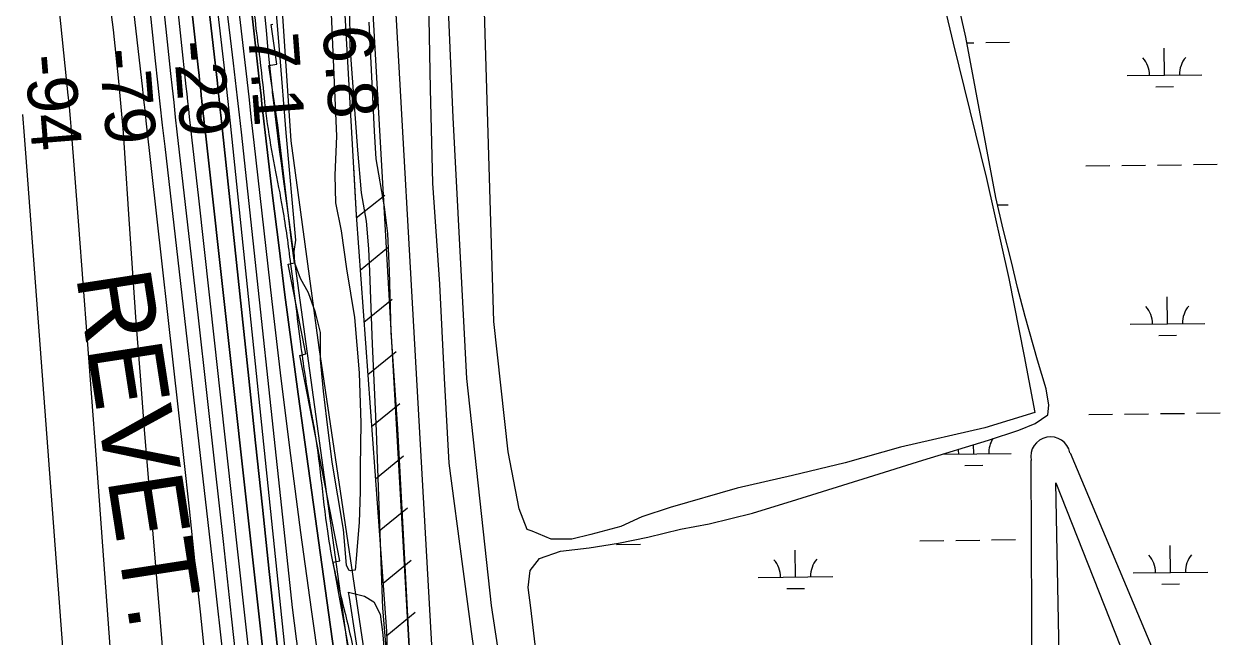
# Model space of a CAD drawing. Extents: x 3694830 to 3732949, y 415201 to 440970.
# Drawn here: x 3718390 to 3720008, y 423717 to 424536 of the extents above; entities that cross this region are included whole.
import ezdxf

# ---------------------------------------------------------------- set-up
doc = ezdxf.new("R2010")
doc.units = 0
for name, color, linetype in [('V-FLOD-BASE', 7, 'Continuous'), ('V-LEVE-TOET', 7, 'Continuous'), ('V-RIVR-EDGE', 7, 'Continuous'), ('V-RIVR-RANG', 7, 'Continuous'), ('V-ROAD-CNTR', 7, 'Continuous'), ('V-RRAP-FSHR', 7, 'Continuous'), ('V-RRAP-RVMT', 7, 'Continuous'), ('V-RRAP-RVMT-IDEN', 7, 'Continuous'), ('V-SITE-VEGE', 7, 'Continuous'), ('V-SURV-LINE', 7, 'Continuous'), ('V-TOPO-DPTH', 7, 'Continuous'), ('V-TOPO-MAJR', 7, 'Continuous'), ('V-TOPO-MINR', 7, 'Continuous'), ('V-TOPO-WATR', 7, 'Continuous'), ('V-TOPO-WATR-IDEN', 7, 'Continuous'), ('V-WETL-SWMP', 7, 'Continuous')]:
    doc.layers.add(name, color=color, linetype=linetype)

msp = doc.modelspace()

# ---------------------------------------------------------------- linework, layer by layer
at = {"layer": 'V-FLOD-BASE'}
msp.add_lwpolyline([(3719080, 422624.3), (3719063, 422730.6), (3719042.5, 422855.9), (3719023.9, 422955), (3718998.7, 423105.1), (3718976, 423242.3), (3718950.3, 423388.8), (3718931.8, 423489.9), (3718918.9, 423582.8), (3718912.7, 423621.4), (3718909.6, 423642.6), (3718908.1, 423662.7), (3718904.5, 423727.2), (3718897.9, 423854.1), (3718890.2, 423994.9), (3718881.4, 424124.4), (3718878.9, 424206.4), (3718876.9, 424256.4), (3718872.2, 424292), (3718861.4, 424356), (3718858.8, 424393.1), (3718851.7, 424539.1)], dxfattribs=at)
at = {"layer": 'V-LEVE-TOET'}
for points in [[(3719118.2, 422780.4), (3719107.6, 422885.7), (3719094.9, 423003.7), (3719080, 423116.4), (3719049.3, 423317.4), (3719031.2, 423440.8), (3719014.3, 423552.4), (3718999.4, 423646), (3718988.8, 423723.6), (3718977.1, 423810.8), (3718959.1, 423949.1), (3718952.8, 424062.8), (3718946.4, 424188.3), (3718936.9, 424323.4), (3718933.8, 424449.9), (3718931.7, 424566.9), (3718926.4, 424699.8), (3718917.9, 424783.8), (3718910.5, 424881.6), (3718901, 424966.7), (3718901, 425006.1), (3718898.9, 425044.3), (3718900, 425078.4)], [(3718995.1, 422968.1), (3718965.4, 423137.2), (3718928.2, 423349.9), (3718893.2, 423534.9), (3718884.7, 423580.7), (3718880.5, 423621.1), (3718877.3, 423670), (3718869.9, 423755.1), (3718865.7, 423879.5), (3718861.5, 423992.2), (3718856.2, 424108.1), (3718852.5, 424205.4), (3718851.4, 424235.7), (3718848.3, 424272.9), (3718841.4, 424310.7), (3718836.6, 424367.6), (3718826.6, 424506.9), (3718825.5, 424612.7)]]:
    msp.add_lwpolyline(points, dxfattribs=at)
at = {"layer": 'V-RIVR-EDGE'}
msp.add_spline([(3716285.2, 433216.7), (3716310.4, 433178.2), (3716330.2, 433149.7), (3716351.4, 433122.5), (3716380.7, 433076.8), (3716399.1, 433050.5), (3716447.8, 432976.2), (3716475.3, 432930.5), (3716501.8, 432891.1), (3716527.5, 432851.2), (3716586, 432749.3), (3716608.1, 432711.8), (3716608.1, 432707.7), (3716608.1, 432700.4), (3716613, 432690.9), (3716627.4, 432664.2), (3716633.3, 432651.6), (3716643.2, 432639.3), (3716675.2, 432589.5), (3716706.2, 432538.3), (3716726.9, 432498), (3716741.3, 432463.6), (3716748.5, 432442.8), (3716788.6, 432378.5), (3716817.4, 432339.6), (3716842.2, 432297.4), (3716889.5, 432209.6), (3716920.5, 432144.4), (3716938, 432109.6), (3716956.5, 432075.2), (3716988.9, 432022.6), (3717009.2, 431986.9), (3717026.3, 431960.1), (3717062.3, 431897.6), (3717093.4, 431840.1), (3717112.3, 431799.9), (3717149.1, 431711.1), (3717176.5, 431644.6), (3717201.2, 431580.8), (3717210.7, 431556.4), (3717248.5, 431478.9), (3717267.8, 431435.5), (3717289.4, 431392.9), (3717306.5, 431346.8), (3717328.1, 431301), (3717339.3, 431276.6), (3717352.3, 431244), (3717362.7, 431226.4), (3717376.2, 431205.5), (3717389.3, 431178.4), (3717401.4, 431141.7), (3717407.2, 431113.2), (3717409.9, 431101.9), (3717419.7, 431075.6), (3717452.5, 430968.9), (3717469.1, 430916.8), (3717483.4, 430865.2), (3717505.5, 430810), (3717526.6, 430753.4), (3717540.5, 430715.4), (3717579.1, 430593.2), (3717599.3, 430526.3), (3717616.3, 430474.7), (3717628.9, 430437.1), (3717638.7, 430405), (3717647.7, 430364.3), (3717653.5, 430331.7), (3717658.4, 430314.5), (3717667.9, 430290.1), (3717679.5, 430260.7), (3717690.3, 430242.1), (3717695.7, 430221.3), (3717698.4, 430200), (3717697.9, 430172), (3717701.4, 430153), (3717705.9, 430140.8), (3717716.3, 430119.9), (3717728, 430100.5), (3717735.6, 430076.5), (3717737.8, 430059.3), (3717749, 430029.9), (3717760.8, 430011.8), (3717771.6, 429990), (3717776.5, 429968.3), (3717783.2, 429941.6), (3717791.7, 429917.6), (3717803.4, 429898.6), (3717812.4, 429876.5), (3717819.2, 429857.4), (3717834.9, 429816.7), (3717846.5, 429770.1), (3717854.1, 429734.8), (3717863.5, 429706.3), (3717878.8, 429667.4), (3717891.4, 429622.6), (3717903.5, 429586.4), (3717917.8, 429530.3), (3717931.7, 429476.4), (3717959.5, 429363.8), (3717976.5, 429307.2), (3717987.2, 429262.4), (3718014.1, 429153.9), (3718027.5, 429090.1), (3718040.5, 429028.1), (3718052.5, 428962.5), (3718057.8, 428920), (3718056.9, 428903.3), (3718056.9, 428887.9), (3718057.7, 428868.4), (3718061.3, 428850.8), (3718065.8, 428833.6), (3718082.4, 428779.3), (3718091.3, 428748.1), (3718100.3, 428711), (3718111.4, 428657.1), (3718116.4, 428631.8), (3718128.3, 428526), (3718136.8, 428473.1), (3718141.7, 428440), (3718152.3, 428360.9), (3718163.9, 428291.2), (3718171, 428256.4), (3718178.2, 428236.5), (3718193.9, 428178.6), (3718199.7, 428157.3), (3718197.9, 428150.1), (3718196.5, 428133.3), (3718197.4, 428121.1), (3718204.1, 428098), (3718215.4, 428075.4), (3718228, 428049.6), (3718240.1, 428011.6), (3718242.7, 427978.6), (3718251.1, 427901.2), (3718254.2, 427852.9), (3718257.7, 427822.1), (3718271.5, 427736.2), (3718281.7, 427671.9), (3718287.9, 427606.3), (3718295.9, 427551.6), (3718303.9, 427477.4), (3718310.1, 427447.1), (3718323.1, 427407.8), (3718345.1, 427350.3), (3718351.4, 427321.8), (3718363.5, 427267.5), (3718378.3, 427217.3), (3718398, 427141.2), (3718402.9, 427105.5), (3718405.9, 427056.7), (3718404.9, 426993.4), (3718419.6, 426915.1), (3718427.1, 426857.7), (3718428.8, 426789.8), (3718439.5, 426753.2), (3718453.9, 426709.8), (3718458.3, 426677.2), (3718461.8, 426625.2), (3718465.3, 426583.6), (3718482.7, 426479.5), (3718492.5, 426423.9), (3718501, 426378.2), (3718502.7, 426350.2), (3718512.9, 426256.1), (3718518.2, 426213.1), (3718524, 426182.8), (3718533.4, 426148.9), (3718540.9, 426069.3), (3718548.9, 426010.9), (3718557.8, 425944.4), (3718573.4, 425858.9), (3718584.5, 425787.5), (3718587.6, 425745.4), (3718587.6, 425726), (3718607.5, 425567.2), (3718614.6, 425488.1), (3718638.2, 425368.6), (3718641.3, 425318.4), (3718641.1, 425249.7), (3718640.1, 425214), (3718649.8, 425130.8), (3718658.7, 425069.3), (3718661.8, 425037.2), (3718660.4, 425016.4), (3718675, 424864.4), (3718675.7, 424812.8), (3718692.6, 424694.8), (3718696.1, 424618.8), (3718696.4, 424575.9), (3718706.1, 424484.5), (3718711.9, 424431.6), (3718715.4, 424403.1), (3718735.9, 424289.1), (3718746.6, 424215.4), (3718759.9, 424108.6), (3718772.4, 424027.2), (3718777.7, 423998.3), (3718795.9, 423858), (3718805.7, 423804.2), (3718812.4, 423776.6), (3718829, 423707.4), (3718835.7, 423662.6), (3718835.1, 423612), (3718835, 423576.7), (3718839.3, 423505.3), (3718842.4, 423460), (3718850.4, 423412.5), (3718863.4, 423357.8), (3718870.6, 423326.6), (3718873.6, 423260.5), (3718878.9, 423209), (3718893.6, 423148.4), (3718899, 423126.2), (3718912.4, 423080), (3718927.2, 423022.6), (3718930.8, 422992.7), (3718937.4, 422950.2), (3718945.9, 422900.5), (3718952.6, 422870.6), (3718968.7, 422795.9), (3718969.6, 422769.7), (3718968.1, 422738.5), (3718972.1, 422707.8), (3718981, 422661.2), (3718990.8, 422602.8), (3719006.9, 422506.5), (3719010.8, 422446.3), (3719014.4, 422425.1), (3719022.4, 422393.4), (3719033.2, 422359), (3719050.3, 422307.9), (3719062.8, 422249.1), (3719077.1, 422190.2), (3719087.8, 422149.1)], degree=3, dxfattribs=at)
at = {"layer": 'V-ROAD-CNTR'}
msp.add_lwpolyline([(3718947.5, 424793.9), (3718964, 424411.4), (3718982.2, 424062.3), (3719015.2, 423758.3), (3719087.3, 423283.5), (3719154, 422831.8), (3719191.5, 422587.8), (3719255.9, 422328.3), (3719350.6, 422063.9), (3719444.2, 421874.4), (3719568.8, 421676.5), (3719728.1, 421465.7), (3719881.2, 421306.9), (3720024.6, 421178.6), (3720151.9, 421084.4), (3720292.9, 420993.4), (3720460.7, 420905.9), (3720538.9, 420876)], dxfattribs=at)
at = {"layer": 'V-RRAP-FSHR'}
for p, q in [((3718834.5, 424277.1), (3718872.9, 424307.3)), ((3718839.7, 424207.3), (3718877.6, 424238.2)), ((3718844.8, 424137.5), (3718882.7, 424168.3)), ((3718849.9, 424067.7), (3718887.8, 424098.5)), ((3718855, 423997.9), (3718892.9, 424028.7)), ((3718860.1, 423928.1), (3718898, 423958.9)), ((3718865.2, 423858.3), (3718903.1, 423889.1)), ((3718870.4, 423788.4), (3718908.2, 423819.3)), ((3718875.5, 423718.6), (3718913.3, 423749.5))]:
    msp.add_line(p, q, dxfattribs=at)
for points in [[(3718391.1, 427348.3), (3718475.5, 426733.1), (3718537.6, 426315.3), (3718574.7, 426010.6), (3718621.1, 425693.6), (3718655.8, 425402.4), (3718689.1, 424990.9), (3718733.5, 424580.7), (3718747, 424380.1), (3718784.4, 424103.6), (3718845.2, 423695.1), (3718886.1, 423421.6), (3718923.4, 423190.5), (3718957.4, 423026.2), (3718988.3, 422871.6), (3719013.6, 422718), (3719111.7, 422210.5), (3719157, 422005.7), (3719219.8, 421828), (3719374.7, 421477.8), (3719529.6, 421100.8)], [(3718800.8, 424873.2), (3718834.3, 424280.7), (3718875.1, 423724.2), (3718879.1, 423600.7), (3718900.6, 423436), (3718998.4, 422905.1), (3719048.2, 422575.2), (3719088.2, 422325.5), (3719124.8, 422190.6), (3719167, 422050.6), (3719263.7, 421833.4), (3719401.6, 421600.1), (3719571.7, 421363.5), (3719742.7, 421175.3), (3719823.1, 421106.3)], [(3718830.7, 424345.4), (3718834.3, 424280.7), (3718875.1, 423724.2), (3718878, 423633.2)]]:
    msp.add_lwpolyline(points, dxfattribs=at)
at = {"layer": 'V-RRAP-RVMT'}
for p, q in [((3718720.7, 424535.9), (3718722.9, 424536.3)), ((3718728.2, 424482.9), (3718720.7, 424535.9)), ((3718717.4, 424480.9), (3718728.2, 424482.9)), ((3718729.7, 424401.2), (3718717.4, 424480.9)), ((3718747.9, 424246.5), (3718729.7, 424401.2)), ((3718752, 424216.9), (3718747.9, 424246.5)), ((3718743.2, 424215), (3718752, 424216.9)), ((3718767.2, 424095.2), (3718743.2, 424215)), ((3718759, 424093), (3718767.2, 424095.2)), ((3718812.5, 423818.3), (3718759, 424093)), ((3718803.8, 423816.5), (3718812.5, 423818.3)), ((3718825.9, 423693.4), (3718803.8, 423816.5))]:
    msp.add_line(p, q, dxfattribs=at)
at = {"layer": 'V-SITE-VEGE'}
for points in [[(3719580.5, 424734), (3719633.6, 424510.7), (3719678.2, 424329.9), (3719707.9, 424195.9), (3719728.5, 424092.2), (3719742.6, 424016.8), (3719676, 423996), (3719563.2, 423970.5), (3719488.8, 423949.3), (3719418.6, 423932.3), (3719344.2, 423915.3), (3719254.8, 423889.8), (3719216.6, 423877), (3719188.9, 423864.3), (3719148.5, 423853.7), (3719123, 423847.3), (3719095.3, 423847.3), (3719069.8, 423858), (3719063.4, 423860.1), (3719052.8, 423887.7), (3719037.9, 423964.3), (3719018.9, 424138.7), (3719006.3, 424553.4)], [(3718798.4, 424611.9), (3718807.9, 424386.5), (3718805.7, 424334.4), (3718806.8, 424297.2), (3718814.2, 424259.9), (3718821.6, 424208.9), (3718832.3, 424144), (3718838.6, 424069.6), (3718840.7, 424002.6), (3718839.6, 423944.1), (3718839.6, 423911.1), (3718838.5, 423869.7), (3718836.4, 423843.1), (3718834.3, 423820.8), (3718833.2, 423805.9), (3718826.8, 423804.8), (3718824.7, 423805.9), (3718821.5, 423812.3), (3718817.3, 423860.1), (3718802.4, 423950.5), (3718795, 424007.9), (3718790.8, 424045.1), (3718786.5, 424087.7), (3718786.5, 424123.8), (3718780.2, 424150.4), (3718770.6, 424177), (3718760, 424196.2), (3718752.5, 424216.4), (3718751.5, 424232.3), (3718753.6, 424247.2), (3718740.9, 424390.8), (3718732.4, 424497.1), (3718714.4, 424710.8)]]:
    msp.add_lwpolyline(points, dxfattribs=at)
at = {"layer": 'V-SURV-LINE'}
for points in [[(3718860.6, 425023.9), (3718941.6, 423595.4)], [(3718911.6, 423593.7), (3718830.6, 425022.2)]]:
    msp.add_lwpolyline(points, dxfattribs=at)
at = {"layer": 'V-TOPO-DPTH'}
for points in [[(3718536.6, 425258.5), (3718623.3, 424474.8), (3718624.1, 424468.1), (3718624.8, 424461.3), (3718625.6, 424454.5), (3718626.3, 424447.7), (3718627.6, 424436), (3718627.7, 424435.1), (3718627.8, 424434.1), (3718627.9, 424433.2), (3718628, 424432.3), (3718629.1, 424422.2), (3718629.8, 424416.3), (3718630.4, 424410.3), (3718631.1, 424404.4), (3718631.7, 424398.4), (3718722.8, 423578.2)], [(3718536.6, 425258.5), (3718623.3, 424474.8), (3718624.1, 424468.1), (3718624.8, 424461.3), (3718625.6, 424454.5), (3718626.3, 424447.7), (3718627.6, 424436), (3718627.7, 424435.1), (3718627.8, 424434.1), (3718627.9, 424433.2), (3718628, 424432.3), (3718629.1, 424422.2), (3718629.8, 424416.3), (3718630.4, 424410.3), (3718631.1, 424404.4), (3718631.7, 424398.4), (3718722.8, 423578.2)], [(3719042.8, 422082), (3718907.4, 422824.3), (3718862.2, 423105.4), (3718849.9, 423179.3), (3718836.9, 423253.1), (3718823.1, 423326.7), (3718808.6, 423400.2), (3718794.8, 423468.2), (3718787.1, 423507.7), (3718779.8, 423547.2), (3718773.1, 423586.8), (3718766.8, 423626.5), (3718766.2, 423630.4), (3718760.2, 423672.1), (3718754.5, 423713.9), (3718749.4, 423755.7), (3718744.6, 423797.6), (3718680.8, 424391.8), (3718678.3, 424414.8), (3718675.7, 424437.8), (3718673, 424460.9), (3718670.3, 424483.9), (3718583, 425211.4)], [(3719042.8, 422082), (3718907.4, 422824.3), (3718862.2, 423105.4), (3718849.9, 423179.3), (3718836.9, 423253.1), (3718823.1, 423326.7), (3718808.6, 423400.2), (3718794.8, 423468.2), (3718787.1, 423507.7), (3718779.8, 423547.2), (3718773.1, 423586.8), (3718766.8, 423626.5), (3718766.2, 423630.4), (3718760.2, 423672.1), (3718754.5, 423713.9), (3718749.4, 423755.7), (3718744.6, 423797.6), (3718680.8, 424391.8), (3718678.3, 424414.8), (3718675.7, 424437.8), (3718673, 424460.9), (3718670.3, 424483.9), (3718583, 425211.4)], [(3718627, 424647.6), (3718648.6, 424457.2), (3718649.8, 424446.6), (3718651, 424435.9), (3718652.1, 424425.3), (3718653.3, 424414.6), (3718690.7, 424062.2), (3718699.9, 423976.2), (3718709.1, 423890.1), (3718718.2, 423804.1), (3718727.4, 423718.1), (3718744.3, 423559.5)], [(3718744.3, 423559.5), (3718727.4, 423718.1), (3718718.2, 423804.1), (3718709.1, 423890.1), (3718699.9, 423976.2), (3718690.7, 424062.2), (3718653.3, 424414.6), (3718652.1, 424425.3), (3718651, 424435.9), (3718649.8, 424446.6), (3718648.6, 424457.2), (3718627, 424647.6)], [(3718689.2, 424604.5), (3718704.6, 424462.5), (3718705.8, 424451.4), (3718707.1, 424440.3), (3718708.3, 424429.2), (3718709.6, 424418.1), (3718722.6, 424307.2), (3718730.7, 424240.7), (3718739, 424174.2), (3718747.7, 424107.8), (3718756.7, 424041.4), (3718820.4, 423582.2)], [(3718701.9, 423596.3), (3718652.5, 424044.6), (3718645.4, 424109.3), (3718638.2, 424174), (3718631, 424238.7), (3718623.7, 424303.4), (3718611.5, 424412.3), (3718610.3, 424422.5), (3718609.2, 424432.7), (3718608.1, 424442.9), (3718607, 424453.1), (3718593.5, 424579.9)], [(3718701.9, 423596.3), (3718652.5, 424044.6), (3718645.4, 424109.3), (3718638.2, 424174), (3718631, 424238.7), (3718623.7, 424303.4), (3718611.5, 424412.3), (3718610.3, 424422.5), (3718609.2, 424432.7), (3718608.1, 424442.9), (3718607, 424453.1), (3718593.5, 424579.9)]]:
    msp.add_lwpolyline(points, dxfattribs=at)
at = {"layer": 'V-TOPO-MAJR'}
for points in [[(3718681.9, 423613.8), (3718667.7, 423744.1), (3718656.7, 423844), (3718645.7, 423943.8), (3718634.5, 424043.6), (3718623.3, 424143.4), (3718595, 424392.3), (3718592.8, 424411.8), (3718590.7, 424431.3), (3718588.5, 424450.7), (3718586.5, 424470.2), (3718549.4, 424821.9)], [(3718445.6, 423649.3), (3718392.7, 424357.7), (3718390.4, 424386.7), (3718388.2, 424415.6)]]:
    msp.add_lwpolyline(points, dxfattribs=at)
at = {"layer": 'V-TOPO-MINR'}
for points in [[(3718722.8, 423578.2), (3718631.7, 424398.4), (3718631.1, 424404.4), (3718630.4, 424410.3), (3718629.8, 424416.3), (3718629.1, 424422.2), (3718628, 424432.3), (3718627.9, 424433.2), (3718627.8, 424434.1), (3718627.7, 424435.1), (3718627.6, 424436), (3718626.3, 424447.7), (3718625.6, 424454.5), (3718624.8, 424461.3), (3718624.1, 424468.1), (3718623.3, 424474.8), (3718536.6, 425258.5)], [(3719042.8, 422082), (3718907.4, 422824.3), (3718862.2, 423105.4), (3718849.9, 423179.3), (3718836.9, 423253.1), (3718823.1, 423326.7), (3718808.6, 423400.2), (3718794.8, 423468.2), (3718787.1, 423507.7), (3718779.8, 423547.2), (3718773.1, 423586.8), (3718766.8, 423626.5), (3718766.2, 423630.4), (3718760.2, 423672.1), (3718754.5, 423713.9), (3718749.4, 423755.7), (3718744.6, 423797.6), (3718680.8, 424391.8), (3718678.3, 424414.8), (3718675.7, 424437.8), (3718673, 424460.9), (3718670.3, 424483.9), (3718583, 425211.4)], [(3718658, 423675.5), (3718653.2, 423719.3), (3718648.3, 423763.1), (3718643.4, 423807), (3718578.6, 424372.4), (3718575.3, 424401.1), (3718572.1, 424429.8), (3718569, 424458.6), (3718566, 424487.3), (3718491.6, 425199.3)], [(3718796.1, 423602.5), (3718774.7, 423753.3), (3718760.5, 423856.2), (3718746.9, 423959.1), (3718734.2, 424062.1), (3718722.1, 424165.2), (3718698, 424377.8), (3718694.5, 424408.4), (3718691, 424439), (3718687.5, 424469.7), (3718684, 424500.3), (3718632, 424949.1)], [(3718740.7, 423686.5), (3718666.3, 424403.7), (3718664.6, 424420.3), (3718662.8, 424436.8), (3718660.9, 424453.4), (3718659, 424470), (3718605.2, 424933.5)], [(3718514, 423581.6), (3718486.3, 423960.1), (3718480.6, 424036.8), (3718474.9, 424113.6), (3718469.1, 424190.3), (3718463.2, 424267), (3718452.9, 424399.4), (3718452.1, 424409.9), (3718451.2, 424420.4), (3718450.2, 424431), (3718449.1, 424441.5), (3718415.1, 424773.2)], [(3718633.4, 423681), (3718626.1, 423749.9), (3718618.7, 423818.8), (3718611.2, 423887.7), (3718603.6, 423956.6), (3718553.5, 424407), (3718552.3, 424417.6), (3718551.1, 424428.2), (3718549.9, 424438.8), (3718548.7, 424449.3), (3718527.5, 424636.1)], [(3718744.3, 423559.5), (3718727.4, 423718.1), (3718718.2, 423804.1), (3718709.1, 423890.1), (3718699.9, 423976.2), (3718690.7, 424062.2), (3718653.3, 424414.6), (3718652.1, 424425.3), (3718651, 424435.9), (3718649.8, 424446.6), (3718648.6, 424457.2), (3718627, 424647.6)], [(3718701.9, 423596.3), (3718652.5, 424044.6), (3718645.4, 424109.3), (3718638.2, 424174), (3718631, 424238.7), (3718623.7, 424303.4), (3718611.5, 424412.3), (3718610.3, 424422.5), (3718609.2, 424432.7), (3718608.1, 424442.9), (3718607, 424453.1), (3718593.5, 424579.9)], [(3718582.6, 423612.1), (3718551.3, 423994.1), (3718545.6, 424066), (3718540.1, 424137.9), (3718535, 424209.9), (3718530.2, 424281.9), (3718525.3, 424356.9), (3718522.9, 424391.4), (3718520.1, 424425.8), (3718516.9, 424460.2), (3718513.3, 424494.5), (3718509.4, 424528.8), (3718505.3, 424563.1)], [(3718842.4, 423563.6), (3718736.8, 424332.3), (3718734.3, 424350.5), (3718731.9, 424368.7), (3718729.6, 424386.9), (3718727.4, 424405.1), (3718723.7, 424435.2), (3718723.3, 424438.3), (3718723, 424441.5), (3718722.6, 424444.7), (3718722.3, 424447.9), (3718718.5, 424484.9), (3718716.3, 424506.6), (3718714.2, 424528.4), (3718712.2, 424550.1)]]:
    msp.add_lwpolyline(points, dxfattribs=at)
at = {"layer": 'V-TOPO-WATR'}
msp.add_lwpolyline([(3718820.4, 423582.2), (3718756.7, 424041.4), (3718747.7, 424107.8), (3718739, 424174.2), (3718730.7, 424240.7), (3718722.6, 424307.2), (3718709.6, 424418.1), (3718708.3, 424429.2), (3718707.1, 424440.3), (3718705.8, 424451.4), (3718704.6, 424462.5), (3718689.2, 424604.5)], dxfattribs=at)
at = {"layer": 'V-TOPO-WATR-IDEN'}
for points in [[(3719789.9, 423962.9), (3719908.3, 423681.4), (3720050.2, 423709.9), (3720175.9, 423083.8), (3720034, 423055.3), (3720035.4, 422740.2)], [(3719983.4, 422729.8), (3719860.9, 423031.4), (3719820.9, 423230.8), (3719668.6, 423200.3), (3719631.4, 423385.6), (3719783.7, 423416.2), (3719739.4, 423636.7), (3719737.9, 423952.5)], [(3719776, 423669), (3719770.9, 423922.8), (3719864.2, 423686.7)]]:
    msp.add_lwpolyline(points, dxfattribs=at)
msp.add_arc((3719763.9, 423957.7), 26.5, 11.3511, 191.3511, dxfattribs=at)
at = {"layer": 'V-WETL-SWMP'}
for p, q in [((3719650.6, 424518.7), (3719617.5, 424664.2)), ((3719690.5, 424304.4), (3719650.6, 424518.7)), ((3719652, 424511.3), (3719661.1, 424511.4)), ((3719677.1, 424511.6), (3719709.1, 424512)), ((3719916.5, 424468), (3719916, 424504)), ((3719866.5, 424467.4), (3719966.5, 424468.6)), ((3719904.7, 424452.4), (3719928.6, 424452.7)), ((3719811.1, 424346.7), (3719843.1, 424347.1)), ((3719859.1, 424347.3), (3719891.1, 424347.6)), ((3719907.1, 424347.8), (3719939.1, 424348.2)), ((3719955.1, 424348.4), (3719987, 424348.8)), ((3719700.3, 424262.1), (3719690.5, 424304.4)), ((3719692.8, 424294.5), (3719707.1, 424294.7)), ((3719711.8, 424218.2), (3719700.3, 424262.1)), ((3719719.7, 424183.8), (3719711.8, 424218.2)), ((3719729.9, 424145.1), (3719719.7, 424183.8)), ((3719920.4, 424135.4), (3719920, 424171.4)), ((3719746.5, 424086.6), (3719729.9, 424145.1)), ((3719870.4, 424134.8), (3719970.4, 424136)), ((3719908.6, 424119.8), (3719932.6, 424120.1)), ((3719758, 424048.2), (3719746.5, 424086.6)), ((3719761.5, 424026.5), (3719758, 424048.2)), ((3719760.3, 424013.8), (3719761.5, 424026.5)), ((3719743.3, 424002), (3719760.3, 424013.8)), ((3719815, 424014), (3719847, 424014.4)), ((3719863, 424014.6), (3719895, 424015)), ((3719911, 424015.2), (3719943, 424015.6)), ((3719959, 424015.7), (3719991, 424016.1)), ((3719680.9, 423979.8), (3719721.2, 423993.3)), ((3719721.2, 423993.3), (3719743.3, 424002)), ((3719593.1, 423953), (3719680.9, 423979.8)), ((3719661.1, 423961.4), (3719660.9, 423973.7)), ((3719619.1, 423960.9), (3719711, 423962)), ((3719520.3, 423930.1), (3719593.1, 423953)), ((3719649.2, 423945.9), (3719673.2, 423946.2)), ((3719424.3, 423900.5), (3719520.3, 423930.1)), ((3719364.9, 423881.9), (3719424.3, 423900.5)), ((3719306.8, 423867.7), (3719364.9, 423881.9)), ((3719224.6, 423849.9), (3719268.5, 423860.6)), ((3719268.5, 423860.6), (3719306.8, 423867.7)), ((3719185.4, 423842), (3719224.6, 423849.9)), ((3719589, 423845.1), (3719621, 423845.5)), ((3719637, 423845.7), (3719669, 423846.1)), ((3719685, 423846.3), (3719717, 423846.7)), ((3719079.9, 423821.5), (3719108, 423831)), ((3719108, 423831), (3719146.3, 423835.7)), ((3719146.3, 423835.7), (3719185.4, 423842)), ((3719183.1, 423840.3), (3719215.1, 423840.7)), ((3719422.5, 423796.7), (3719422.1, 423832.7)), ((3719924.4, 423802.7), (3719924, 423838.7)), ((3719067.2, 423805.3), (3719079.9, 423821.5)), ((3719064.8, 423782.4), (3719067.2, 423805.3)), ((3719372.5, 423796.1), (3719472.5, 423797.3)), ((3719874.4, 423802.1), (3719974.4, 423803.3)), ((3719068, 423755.5), (3719064.8, 423782.4)), ((3719410.7, 423781.2), (3719434.7, 423781.4)), ((3719912.6, 423787.1), (3719936.6, 423787.4)), ((3719075.5, 423695.4), (3719068, 423755.5))]:
    msp.add_line(p, q, dxfattribs=at)
msp.add_lwpolyline([(3718842.5, 423658.4), (3718825.6, 423769), (3718824.3, 423776.4), (3718845.7, 423771.1), (3718858, 423763.2), (3718866.7, 423747), (3718870.2, 423719.3), (3718878.9, 423611.4)], dxfattribs=at)
for centre, start, end in [((3719861.2, 424467.8), 359.9115, 41.4552), ((3719971.7, 424469.2), 139.9115, 181.4552), ((3719865.2, 424135.2), 359.9115, 41.4552), ((3719975.7, 424136.5), 139.9115, 181.4552), ((3719716.3, 423962.6), 146.9701, 181.4552), ((3719605.8, 423961.3), 359.9115, 10.1752), ((3719979.6, 423803.8), 139.9115, 181.4552), ((3719367.3, 423796.5), 359.9115, 41.4552), ((3719477.8, 423797.9), 139.9115, 181.4552), ((3719869.2, 423802.5), 359.9115, 41.4552)]:
    msp.add_arc(centre, 35.2, start, end, dxfattribs=at)

# ---------------------------------------------------------------- texts
at = {"layer": 'V-RIVR-RANG'}
for s, rotation, p in [('7.1', 274.2883, (3718689.7, 424522.4)), ('6.8', 274.2883, (3718789.2, 424532.5)), ('-29', 274.5755, (3718589.7, 424512.6)), ('-94', 274.5755, (3718390.6, 424494)), ('-79', 274.5755, (3718490.3, 424502.2))]:
    msp.add_text(s, height=67, rotation=rotation, dxfattribs=at).set_placement(p)
at = {"layer": 'V-RRAP-RVMT-IDEN'}
msp.add_text('REVET.', height=100, rotation=278.7705, dxfattribs=at).set_placement((3718459.2, 424199.7))

doc.saveas('drawing.dxf')
